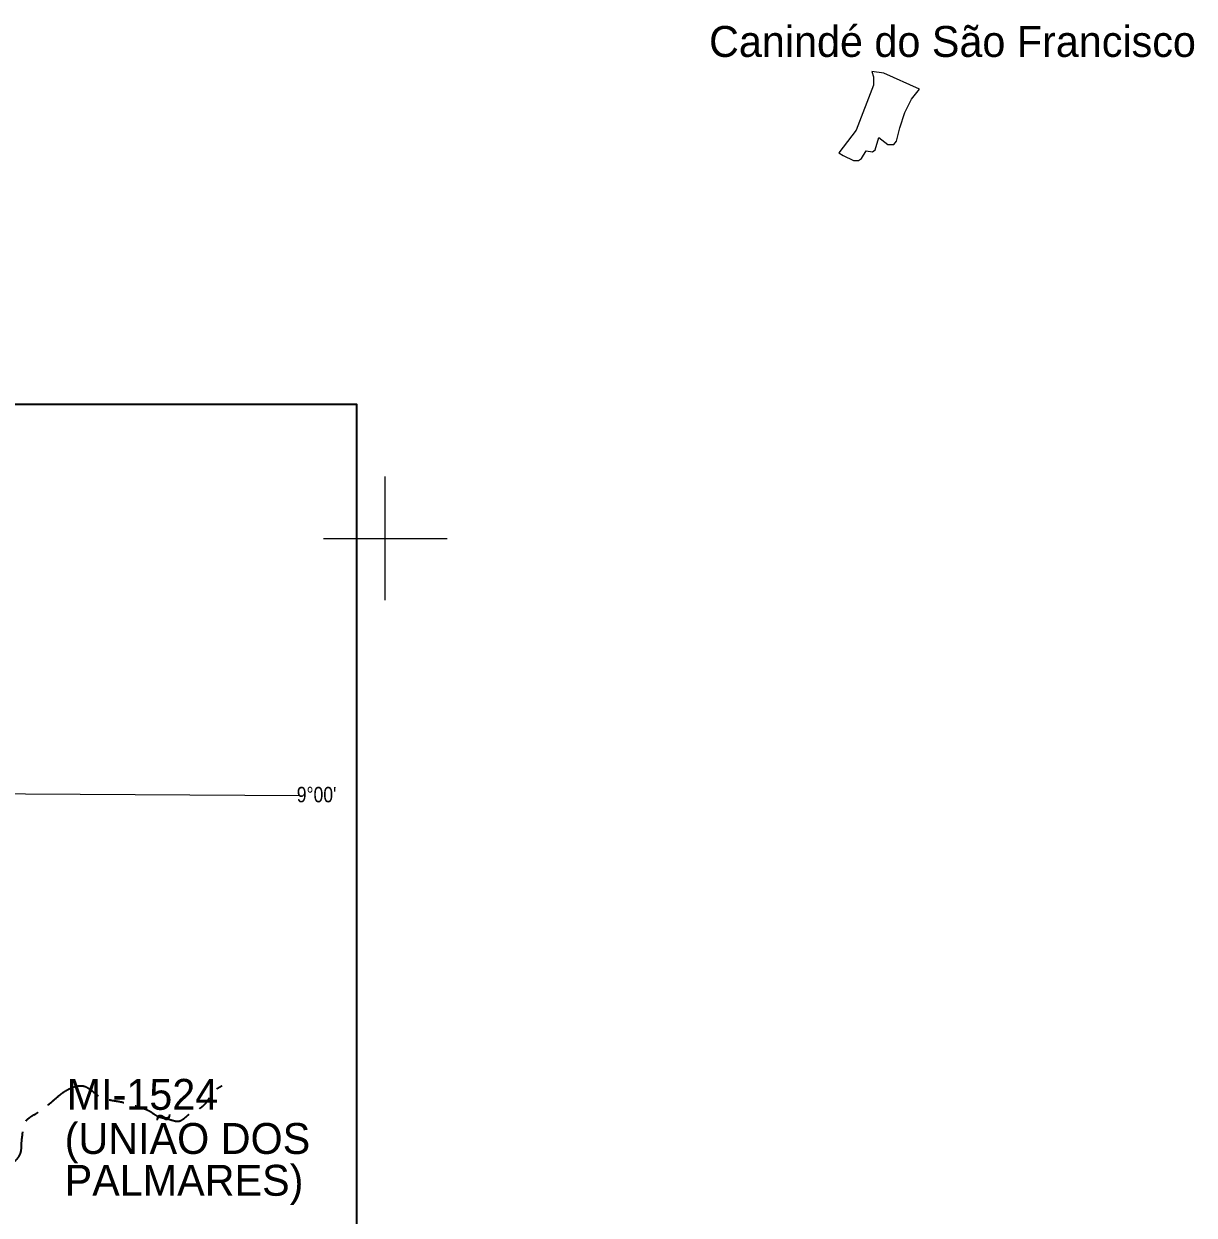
# Model space of a CAD drawing. Extents: x 553962 to 842807, y 8883888 to 9032388.
# Drawn here: x 619151 to 638092, y 8914052 to 8933324 of the extents above; entities that cross this region are included whole.
import ezdxf
from ezdxf.enums import TextEntityAlignment as Align

# ---------------------------------------------------------------- set-up
doc = ezdxf.new("R2010")
doc.units = 0
doc.header["$LTSCALE"] = 160
doc.linetypes.add('LONG_DASH_SHORT_DASH', pattern=[9.9, 6, -1.2, 1.5, -1.2])
for name, color, linetype, lineweight in [('1', 7, 'Continuous', 13), ('28', 7, 'Continuous', 13), ('6', 7, 'Continuous', 13)]:
    doc.layers.add(name, color=color, linetype=linetype, lineweight=lineweight)
doc.layers.add('29', color=7, linetype='Continuous')

msp = doc.modelspace()

# ---------------------------------------------------------------- linework, layer by layer
at = {"layer": '1'}
for p, q in [((625000, 8924000), (625000, 8926000)), ((624000, 8925000), (626000, 8925000))]:
    msp.add_line(p, q, dxfattribs=at)
at = {"layer": '28', "lineweight": 25}
msp.add_lwpolyline([(632873, 8932551.1), (632900.9, 8932464.8), (632903.5, 8932330.2), (632621.7, 8931606.7), (632342.4, 8931238.5), (632413.5, 8931192.8), (632581, 8931114.1), (632657.2, 8931114.1), (632708, 8931147.1), (632781.6, 8931271.5), (632885.7, 8931251.2), (632931.4, 8931286.8), (632989.8, 8931487.3), (633134.5, 8931373.1), (633231, 8931373.1), (633274.1, 8931423.9), (633327.4, 8931639.7), (633411.2, 8931888.5), (633515.3, 8932104.3), (633644.8, 8932266.8), (633071, 8932528.2)], close=True, dxfattribs=at)
at = {"layer": '6', "lineweight": 35}
msp.add_lwpolyline([(576104.8, 8927170.9), (624533.7, 8927170.9), (624533.7, 8897728.1), (576104.8, 8897728.1)], close=True, dxfattribs=at)
at = {"layer": '6'}
msp.add_lwpolyline([(576954.6, 8921057), (596639.8, 8920989.8), (607636.3, 8920937.2), (623613.9, 8920839.1)], dxfattribs=at)
at = {"layer": '6', "linetype": 'LONG_DASH_SHORT_DASH', "lineweight": 35}
msp.add_spline([(618645.2, 8914712.1), (618757.5, 8914863.9), (618920, 8914886.7), (619101.3, 8915065.7), (619114.8, 8915216.7), (619131.1, 8915375.5), (619151.7, 8915505.9), (619183.6, 8915572), (619343.3, 8915692.3), (619623.9, 8915902.9), (619755.5, 8916013.4), (619958, 8916125.3), (620120.4, 8916140.4), (620332.3, 8916000.7), (620548.1, 8915914.9), (620684.2, 8915892), (620903.2, 8915836.8), (621033.8, 8915793.5), (621199.4, 8915729.1), (621321.7, 8915650), (621492.8, 8915605.9), (621656.5, 8915572.3), (621839, 8915694.8), (621982.5, 8915771.8), (622137.8, 8915920.4), (622201, 8916029.6), (622275.9, 8916097.5), (622361, 8916147.5)], degree=3, dxfattribs=at)

# ---------------------------------------------------------------- texts
at = {"layer": '29'}
msp.add_text('Canindé do São Francisco', height=500, dxfattribs=at).set_placement((630240.7, 8932789.3))
at = {"layer": '6', "width": 0.85}
msp.add_text("9°00'", height=250, dxfattribs=at).set_placement((623889, 8920730.7), align=Align.CENTER)
at = {"layer": '6'}
for s, p in [('MI-1524', (619844.4, 8915755.7)), ('(UNIÃO DOS', (619811.5, 8915042.2)), ('PALMARES)', (619811.5, 8914365.8))]:
    msp.add_text(s, height=500, dxfattribs=at).set_placement(p)

doc.saveas('drawing.dxf')
